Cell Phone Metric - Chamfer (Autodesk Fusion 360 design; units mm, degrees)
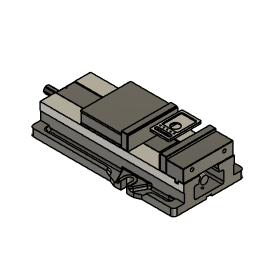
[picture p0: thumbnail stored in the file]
description: HaasClamp
derived_base_feature "Derived Base Feature" bodies "Main Body"
align "Align1"
sketch "Sketch1" plane through (0, 0, 0) normal (0, 0, -1) x axis (1, 0, 0)
  line L1 (30, 46.5) -> (30, -46.5)
  line L2 (-26.5, 50) -> (26.5, 50)
  line L3 (-30, -46.5) -> (-30, 46.5)
  line L4 (26.5, -50) -> (-26.5, -50)
  line L5 (-23.5, 38.5) -> (-23.5, 36)
  line L6 (20, 42) -> (-20, 42)
  line L7 (23.5, 36) -> (23.5, 38.5)
  line L8 (-20, 32.5) -> (20, 32.5)
  line L9 (-50.8, -55) -> (50.8, -55)
  line L10 (-50.8, 55) -> (-50.8, -55)
  line L11 (50.8, 55) -> (-50.8, 55)
  line L12 (50.8, -55) -> (50.8, 55)
  line L13 (-50.8, 55) -> (50.8, -55)
  line L14 (50.8, 55) -> (-50.8, -55)
  arc A1 centre (26.5, -46.5) radius 3.5 clockwise from (30, -46.5) to (26.5, -50)
  arc A2 centre (26.5, 46.5) radius 3.5 clockwise from (26.5, 50) to (30, 46.5)
  arc A3 centre (-26.5, 46.5) radius 3.5 clockwise from (-30, 46.5) to (-26.5, 50)
  arc A4 centre (-26.5, -46.5) radius 3.5 clockwise from (-26.5, -50) to (-30, -46.5)
  circle C1 centre (10.5, 25) radius 2.117
  circle C2 centre (-10.5, 25) radius 2.117
  circle C3 centre (-21, 25) radius 2.117
  circle C4 centre (0, 25) radius 2.117
  circle C5 centre (21, 25) radius 2.117
  arc A5 centre (-20, 38.5) radius 3.5 clockwise from (-23.5, 38.5) to (-20, 42)
  arc A6 centre (20, 38.5) radius 3.5 clockwise from (20, 42) to (23.5, 38.5)
  arc A7 centre (20, 36) radius 3.5 clockwise from (23.5, 36) to (20, 32.5)
  arc A8 centre (-20, 36) radius 3.5 clockwise from (-20, 32.5) to (-23.5, 36)
  circle C6 centre (0, 0) radius 12.5
  point P36 (0, 0)
  point P1 (0, 0)
  point P34 (-50.8, 55)
  point P35 (50.8, 55)
  point P32 (50.8, -55)
  horizontal L9
  perpendicular L9 L10
  parallel L9 L11
  parallel L10 L12
  coincident L13 P36
  coincident L14 P36
  coincident P1 P36
  dimension "d1" distance P34 P35 = 101.6
  dimension "d2" distance P32 P35 = 110
extrude "Extrude1" new body sketch "Sketch1" profile of L9 L10 L11 L12 against normal blind 6 bodies "Stock"
base_feature "Base Feature1"
base_feature "Base Feature1"
base_feature "Base Feature1"
base_feature "Base Feature1"
base_feature "Base Feature1"
base_feature "Base Feature1"
base_feature "Base Feature1"
base_feature "Base Feature1"
base_feature "Base Feature1"
base_feature "Base Feature1"
as_built_joint "As-built1"
as_built_joint "As-built2"
as_built_joint "As-built3"
joint_origin "JointOrigin1" OffsetX 0 OffsetY 0 OffsetZ 0 AngleZ 0
joint "Assemble1" alignAngle 180 alignOffsetX 0 alignOffsetY 0 alignOffsetZ 0 (= "jaw_width_haas_050002") SlideMaximum 22.5 SlideMinimum 0
position "Position1"
sketch "Sketch1" plane through (0, -72.5, 0) normal (0, -1, 0) x axis (1, 0, 0)
  line L1 (75, 73) -> (-75, 73)
  line L2 (76, 74) -> (75, 73)
  line L3 (76, 116.5) -> (76, 74)
  line L4 (75, 117.5) -> (76, 116.5)
  line L5 (-75, 117.5) -> (75, 117.5)
  line L6 (-76, 116.5) -> (-75, 117.5)
  line L7 (-76, 74) -> (-76, 116.5)
  line L8 (-75, 73) -> (-76, 74)
  line L9 (76.4, 114.275) -> (-76, 114.275)
  line L10 (76.4, 73) -> (76.4, 114.275)
  line L11 (-76, 73) -> (76.4, 73)
  line L12 (-76, 114.275) -> (-76, 73)
  circle C1 centre (49.21, 96.8) radius 11
  circle C2 centre (-49.21, 96.8) radius 11
  point P14 (76.4, 73)
  point P12 (-76, 114.275)
  point P13 (76.4, 114.275)
  horizontal L9
  vertical L10
  horizontal L11
  vertical L12
  coincident L1 P14
  coincident L7 P12
  dimension "d16" distance P12 P13 = 152.4
  dimension "d17" distance P13 P14 = 41.275
place_component sketch "Sketch1"
extrude "Extrude1" new body sketch "Sketch1" profile of L1 L2 L3 L7 L8 C1 C2 L9 L11 L12 along normal blind 3.175
place_component sketch "Sketch1"
extrude "Extrude1" sketch "Sketch1" profile of L1 L2 L3 L7 L8 C1 C2 L9 L11 L12 blind -3.175
as_built_joint "As-built5"
as_built_joint "As-built6"
position "Position1"
ground "Pin"
position "Position2"
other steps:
create_component "CreateComponent1"
create_component "CreateComponent2"
create_component "CreateComponent3"
create_component "CreateComponent4"
create_component "CreateComponent5"
create_component "CreateComponent6"
create_component "CreateComponent7"
create_component "CreateComponent8"
create_component "CreateComponent9"
create_component "CreateComponent10"
joint_origin "JointOrigin10"
joint_origin "JointOrigin11"
create_component "CreateComponent11" sketch "Sketch1"
create_component "CreateComponent12" sketch "Sketch1"
create_component "CreateComponent1"
named bodies: "Main Body", "Stock"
